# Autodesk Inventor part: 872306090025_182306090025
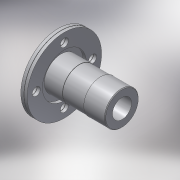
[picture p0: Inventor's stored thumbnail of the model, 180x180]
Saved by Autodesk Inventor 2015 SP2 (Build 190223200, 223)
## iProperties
Created: 2017-02
Part Number: 872306090025_182306090025
Material: PVC-Piping
Description: PLASSON FLANGE ADAPTOR WITH METAL FLANGE 90-2.1/2"
Document SubType Name: Modeling
Designer: KIM
Mass: 92.6774 g
Surface Area: 199.44 cm^2
Volume: 66.1981 cm^3
Density: 1.4 g/cm^3
Appearance: Smooth - White
Author: Кирилл
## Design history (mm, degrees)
derived "872306.ipt"
feature "Solid1::872306.ipt"
tag "TaggingFeature1"
body "Solid1"
other parameters: "d73" = 17.5, "d74" = 90 deg, "d75" = 0.3, "d76" = 185, "d77" = 18, "d78" = 72.5, "d80" = 0, "d82" = 360 deg, "d94" = 65, "d96" = 0.3, "d99" = 360 deg, "d103" = 175, "d104" = 1.8, "d107" = 117, "d108" = 4.375, "d116" = 88.2, "d117" = 58.33333, "d118" = 58.33333, "d120" = 4.5, "H_" = 175, "D_" = 185, "Dp_" = 145, "S_" = 18, "DN_" = 65
